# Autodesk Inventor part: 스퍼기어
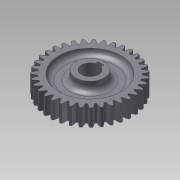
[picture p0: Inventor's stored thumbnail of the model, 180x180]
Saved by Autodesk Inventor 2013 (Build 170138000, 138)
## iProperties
Created: 2013-08
Part Number: 스퍼기어
Material: 강
Document SubType Name: Modeling
Designer: 한국산업디자인학원
Categories: <?xml version="1.0" encoding="UTF-16"?> <MemberInstance><Categories><FamilyTemplate><FamilyTemplateParameter ValueType="xs:double" Id="1" ObjectReferenceKey="da
Density: 1 g/cm^3
CustomPartVersion: 1
Author: 한국산업디자인학원
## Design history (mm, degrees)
sketch "Sketch1"
  geometry: C1 r 37 at (0, 0)
  constraints: 1 centre point
  dimensions: "d0" = 74 diameter of C1 (= da_da)
extrude "Extrusion1" new body sketch "Sketch1" distance "d1" = 15 (= da_b); taper "d2" = 0 deg
workplane "Work Plane2"
feature "피치 지름" dims "d4" = 10, "d5" = 0
workplane "Work Plane8"
workplane "Work Plane9"
feature "스퍼 기어" dims "da_b" = 15, "da_d" = 70, "da_aw" = 70, "da_da" = 74, "da_df" = 65, "da_dw" = 70, angle "da_beta" = 0 deg, "da_lefttooth" = 0, "da_righttooth" = 0
node "작업 평면11"
sketch "스케치4"
  geometry: C1 r 12.5 at (0, 0); 1 further point
  constraints: 1 centre point, 1 coincident
  dimensions: "d51" = 12.5 radius of C1
extrude "돌출2" join sketch "스케치4" distance "d53" = 10.5; taper "d55" = 0 deg; dims "d54" = 20.5, "d56" = 0
sketch "스케치5"
  geometry: C1 r 12.5 at (0, 0) reference; C2 r 27.5 at (0, 0); A1 r 37 centre (0, 0) between (-5.788, 36.544) and (-7.422, 36.248) reference
  constraints: 1 centre point, 1 coincident
  dimensions: "d57" = 55 diameter of C2
extrude "돌출3" cut sketch "스케치5" distance "d60" = 5; taper "d61" = 0 deg
fillet "모깎기1" dims "d62" = 5
sketch "스케치6"
  geometry: L1 (-2.5, 7.071)-(-2.5, 9.8); L2 (-2.5, 9.8)-(2.5, 9.8); L3 (2.5, 9.8)-(2.5, 7.071); C1 r 12.5 at (0, 0) reference; A1 r 7.5 centre (0, 0) between (-2.5, 7.071) and (2.5, 7.071); 1 further point
  constraints: 6 end point, 2 point on circle, 1 centre point, 1 coincident, 1 midpoint, 1 parallel, 1 perpendicular, 1 vertical, 1 vertical alignment
  dimensions: "d63" = 15 diameter of A1; "d65" = 5 distance of L1.end L2.end; "d66" = 17.3 dimension on A1 L2
extrude "돌출4" cut sketch "스케치6" stored distance "d67" = 5; taper "d68" = 0 deg
body "Solid1"
mirror "대칭2"
sketch "Sketch2"
  geometry: C1 r 37 at (0, 0) reference; C2 r 35 at (0, 0)
  constraints: 1 centre point, 1 coincident
  dimensions: "d3" = 70 diameter of C2 (= da_dw)
body "Srf1"
other parameters: "d17" = 0, "d34" = 0.8976 (computed from da_z), "d39" = 0, "d41" = 0, "d47" = 0, "d48" = 0
